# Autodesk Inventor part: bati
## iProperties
Author: robert
Shininess: 21.0
PropertySet Name: _Private Model Information
Compacted: True
Length Units: 11269
Angle Units: 11283
Time Units: 11279
Mass Units: 11290
Length Display Precision: 3
Angle Display Precision: 2
Created: 2001-07
Part Number: bati
Material: Par défaut
Document SubType Name: Modélisation
Designer: robert
Control State: 0
Master: False
Checked Out: False
PropertySet Name: Design Tracking Control
Density: 0.0
Volumn: 0.0
Area: 0.0
PropertySet Name: Model Information
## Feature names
1. Extrusion1
2. Extrusion2
3. Extrusion5
4. Extrusion6
5. Extrusion7
6. Congé1 [Fillet]
7. Perçage1 [Hole]
8. Perçage2 [Hole]
9. Extrusion8
10. Extrusion9
11. Congé2 [Fillet]
12. Perçage3 [Hole]
13. Extrusion10
14. Congé3 [Fillet]
15. Congé4 [Fillet]
16. Congé5 [Fillet]
